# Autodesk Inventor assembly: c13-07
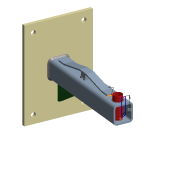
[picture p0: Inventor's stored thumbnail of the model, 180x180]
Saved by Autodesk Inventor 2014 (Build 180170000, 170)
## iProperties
Created: 2011-01
Part Number: c13-07
Document SubType Name: Weldment
Designer: Thom Tremblay
Weld Material: Welded Steel Mild
_SolveAssemblyDoc: Frame Generator Solve Assembly
_Version: 15.0.0
Author: Thom Tremblay
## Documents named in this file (5)
- C:\Inventor 2014 Essentials\Assemblies\Chapter 13\c13-07.iam
- C:\Inventor 2014 Essentials\Parts\Chapter 13\c13-01.ipt
- C:\Inventor 2014 Essentials\Parts\Chapter 13\c13-02.ipt
- C:\Inventor 2014 Essentials\Assemblies\Chapter 13\Frame\Frame c13-01.iam
- C:\Inventor 2014 Essentials\Parts\Chapter 13\c13-03.ipt
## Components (4 placed, 4 different names)
1. c13-01:1 — Mate:2
2. c13-02:1 — Flush:1
3. Frame c13-01:1 [sub-assembly] — Mate:3
4. c13-03:1 — Mate:1, Mate:2, Mate:3
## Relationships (4: Mate 3, Flush 1)
- Flush:1: c13-02:1
- Mate:1: c13-03:1
- Mate:2: c13-01:1 ↔ c13-03:1
- Mate:3: Frame c13-01:1 ↔ c13-03:1
